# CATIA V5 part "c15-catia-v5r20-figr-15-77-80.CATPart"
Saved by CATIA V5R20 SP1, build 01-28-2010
Part number: Part1
Bounding box of the stored display mesh (mm): x -54.135 to 54.135, y -32.893 to 32.893, z -40 to 1
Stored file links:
  D:\v5_r20\psrt_files_downloaded\c15\c15-catia-v5r20-figr-15-77-80.CATPart
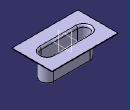
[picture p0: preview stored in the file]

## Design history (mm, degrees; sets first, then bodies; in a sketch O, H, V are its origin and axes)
SheetMetalParameters1: Thickness 1, BendRadius 5, KFactor 0.5 {= log(min(100,max(20*SheetMetalParameters1.BendRadius,SheetMetalParameters1.Thickness)/SheetMetalParameters1.Thickness))/log(100)/2}, ReliefRadialLength 1, ReliefAxialLength 2, MinimumBendRadius 0
Body1 (main body)
  Sketch1 on xy-plane, origin (0, 0, 0), H (1, 0, 0), V (0, 1, 0)
    line L1 (54.1347, 32.8934) -> (54.1347, -32.8934)
    line L2 (54.1347, -32.8934) -> (-54.1347, -32.8934)
    line L3 (-54.1347, -32.8934) -> (-54.1347, 32.8934)
    line L4 (-54.1347, 32.8934) -> (54.1347, 32.8934)
    vertical: L1 V, L3 V
    horizontal: L2 H, L4 H
    equidistance: L1 L3 O, L2 L4 O
    symmetry: L4 L2 H, L3 L1 V
  Wall1: Thickness 1, Profile Sketch1
  Sketch2 on face of Wall1, origin (0, 0, 1), H (1, 0, 0), V (0, 1, 0)
    construction line L1 (-30.4276, 0) -> (29.4134, 0)
    point P1 (-30.4276, 0)
    line L2 (-30.4276, 9.7171) -> (29.4134, 9.7171)
    line L3 (29.4134, -9.7171) -> (-30.4276, -9.7171)
    arc A1 centre (29.4134, 0) radius 9.7171 from (29.4134, 9.7171) to (29.4134, -9.7171) cw
    arc A2 centre (-30.4276, 0) radius 9.7171 from (-30.4276, -9.7171) to (-30.4276, 9.7171) cw
    distance L1 L2 = 9.7171
    coincidence: P1 H
    horizontal: L1 H
    tangency: A1 L2, A2 L2, A1 L3, A2 L3
  d_Stamp1: Stamp_FilletRadius 2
